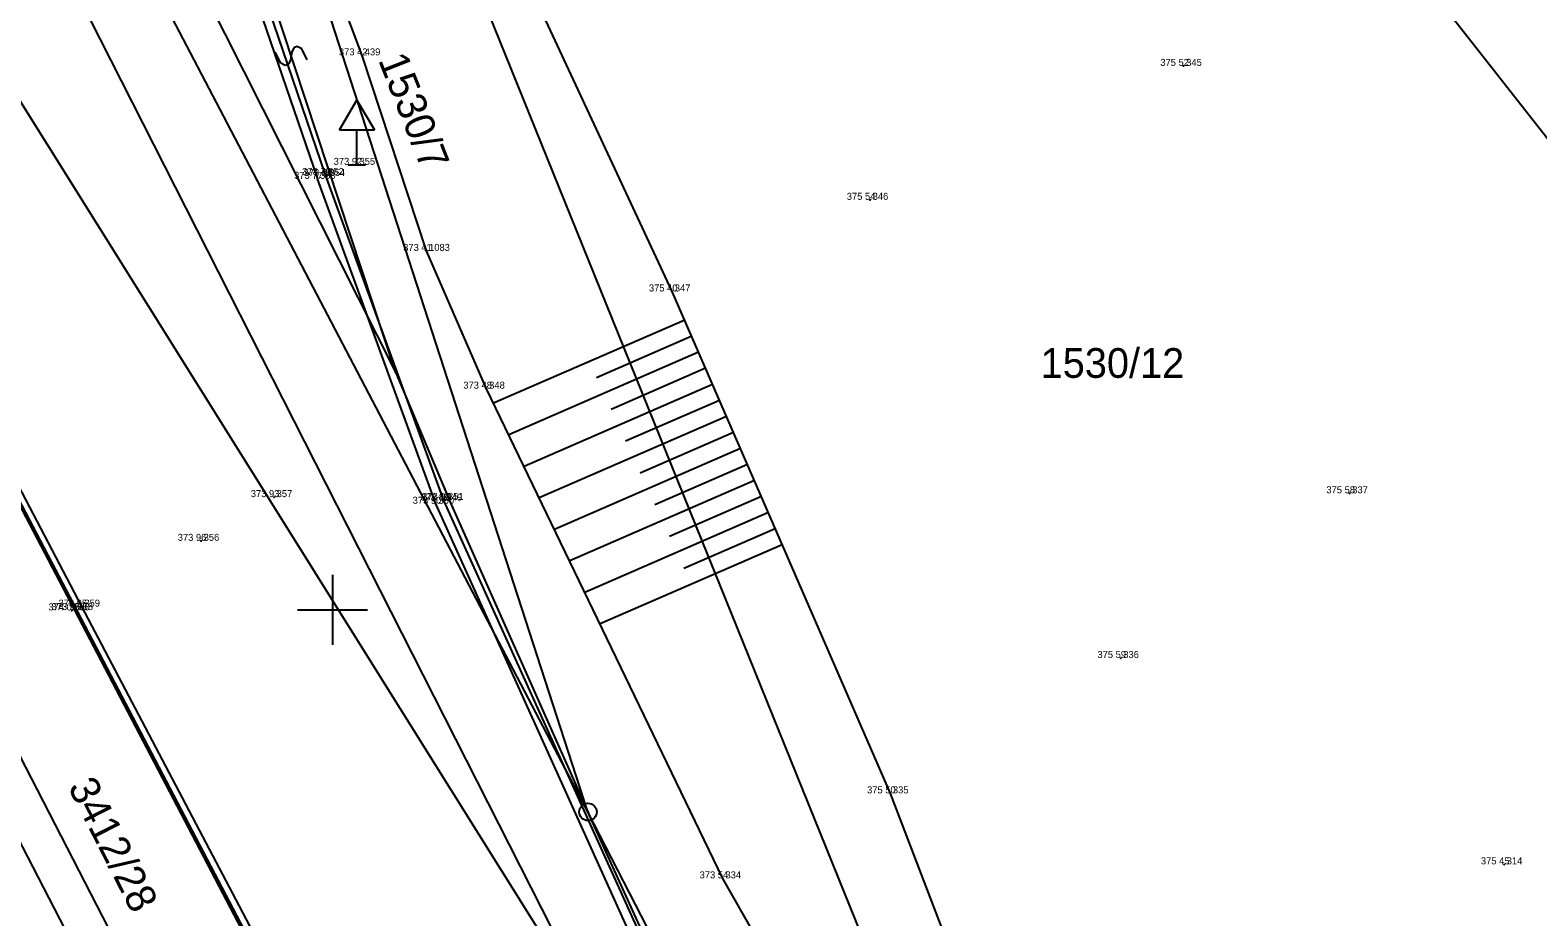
# Model space of a CAD drawing. Extents: x -601196 to -600262, y -1082523 to -1081922.
# Drawn here: x -600508.65 to -600465.52, y -1082258.78 to -1082233.43 of the extents above; entities that cross this region are included whole.
import ezdxf

# ---------------------------------------------------------------- set-up
doc = ezdxf.new("R2010")
doc.units = 0
for name, color, linetype in [('Vrstva 1', 7, 'Continuous'), ('Vrstva 10', 7, 'Continuous'), ('Vrstva 11', 7, 'Continuous'), ('Vrstva 14', 7, 'Continuous'), ('Vrstva 2', 7, 'Continuous'), ('Vrstva 20', 7, 'Continuous'), ('Vrstva 25', 7, 'Continuous'), ('Vrstva 3', 7, 'Continuous'), ('Vrstva 34', 7, 'Continuous'), ('Vrstva 47', 7, 'Continuous'), ('Vrstva 61', 7, 'Continuous')]:
    doc.layers.add(name, color=color, linetype=linetype)

msp = doc.modelspace()

# ---------------------------------------------------------------- linework, layer by layer
at = {"layer": 'Vrstva 1'}
for p, q in [((-600499.15, -1082234.15), (-600499.15, -1082234.15)), ((-600475.65, -1082234.45), (-600475.65, -1082234.45)), ((-600499.3, -1082237.28), (-600499.3, -1082237.28)), ((-600500.43, -1082237.68), (-600500.43, -1082237.68)), ((-600500.2, -1082237.57), (-600500.2, -1082237.57)), ((-600500.16, -1082237.6), (-600500.16, -1082237.6)), ((-600484.62, -1082238.28), (-600484.62, -1082238.28)), ((-600497.31, -1082239.74), (-600497.31, -1082239.74)), ((-600490.28, -1082240.9), (-600490.28, -1082240.9)), ((-600495.59, -1082243.68), (-600495.59, -1082243.68)), ((-600501.67, -1082246.78), (-600501.67, -1082246.78)), ((-600496.81, -1082246.88), (-600496.81, -1082246.88)), ((-600496.77, -1082246.86), (-600496.77, -1082246.86)), ((-600470.9, -1082246.67), (-600470.9, -1082246.67)), ((-600497.04, -1082246.97), (-600497.04, -1082246.97)), ((-600503.76, -1082248.03), (-600503.76, -1082248.03)), ((-600507.17, -1082249.91), (-600507.17, -1082249.91)), ((-600507.46, -1082250.02), (-600507.46, -1082250.02)), ((-600507.37, -1082250.01), (-600507.37, -1082250.01)), ((-600477.45, -1082251.38), (-600477.45, -1082251.38)), ((-600484.04, -1082255.25), (-600484.04, -1082255.25)), ((-600466.48, -1082257.28), (-600466.48, -1082257.28)), ((-600488.83, -1082257.68), (-600488.83, -1082257.68))]:
    msp.add_line(p, q, dxfattribs=at)
at = {"layer": 'Vrstva 10'}
for p, q in [((-600507.37, -1082250.01), (-600522.24, -1082221.66)), ((-600500.2, -1082237.57), (-600505.08, -1082223.28)), ((-600496.81, -1082246.88), (-600500.2, -1082237.57)), ((-600489.75, -1082262.47), (-600496.81, -1082246.88)), ((-600498.3, -1082267.34), (-600507.37, -1082250.01))]:
    msp.add_line(p, q, dxfattribs=at)
at = {"layer": 'Vrstva 11'}
for p, q in [((-600507.17, -1082249.91), (-600522.03, -1082221.55)), ((-600505.32, -1082223.38), (-600500.43, -1082237.68)), ((-600497.04, -1082246.97), (-600500.43, -1082237.68)), ((-600489.97, -1082262.62), (-600497.04, -1082246.97)), ((-600498.04, -1082267.25), (-600507.17, -1082249.91))]:
    msp.add_line(p, q, dxfattribs=at)
at = {"layer": 'Vrstva 14'}
for p, q in [((-600499.15, -1082234.15), (-600503.12, -1082223.58)), ((-600490.28, -1082240.9), (-600494.69, -1082231.44)), ((-600497.31, -1082239.74), (-600499.15, -1082234.15)), ((-600495.59, -1082243.68), (-600497.31, -1082239.74)), ((-600484.04, -1082255.25), (-600490.28, -1082240.9)), ((-600488.83, -1082257.68), (-600495.59, -1082243.68)), ((-600480.39, -1082264.78), (-600484.04, -1082255.25)), ((-600483.98, -1082266.22), (-600488.83, -1082257.68))]:
    msp.add_line(p, q, dxfattribs=at)
at = {"layer": 'Vrstva 20'}
for p, q in [((-600475.66, -1082234.45), (-600475.64, -1082234.45)), ((-600475.65, -1082234.435), (-600475.65, -1082234.45)), ((-600475.65, -1082234.465), (-600475.65, -1082234.45)), ((-600500.17, -1082237.6), (-600500.15, -1082237.6)), ((-600500.16, -1082237.585), (-600500.16, -1082237.6)), ((-600500.16, -1082237.615), (-600500.16, -1082237.6)), ((-600484.63, -1082238.28), (-600484.61, -1082238.28)), ((-600484.62, -1082238.265), (-600484.62, -1082238.28)), ((-600484.62, -1082238.295), (-600484.62, -1082238.28)), ((-600501.68, -1082246.78), (-600501.66, -1082246.78)), ((-600501.67, -1082246.765), (-600501.67, -1082246.78)), ((-600501.67, -1082246.795), (-600501.67, -1082246.78)), ((-600496.78, -1082246.86), (-600496.76, -1082246.86)), ((-600496.77, -1082246.845), (-600496.77, -1082246.86)), ((-600496.77, -1082246.875), (-600496.77, -1082246.86)), ((-600470.91, -1082246.67), (-600470.89, -1082246.67)), ((-600470.9, -1082246.655), (-600470.9, -1082246.67)), ((-600470.9, -1082246.685), (-600470.9, -1082246.67)), ((-600503.77, -1082248.03), (-600503.75, -1082248.03)), ((-600503.76, -1082248.015), (-600503.76, -1082248.03)), ((-600503.76, -1082248.045), (-600503.76, -1082248.03)), ((-600507.47, -1082250.02), (-600507.45, -1082250.02)), ((-600507.46, -1082250.005), (-600507.46, -1082250.02)), ((-600507.46, -1082250.035), (-600507.46, -1082250.02)), ((-600477.46, -1082251.38), (-600477.44, -1082251.38)), ((-600477.45, -1082251.365), (-600477.45, -1082251.38)), ((-600477.45, -1082251.395), (-600477.45, -1082251.38)), ((-600466.49, -1082257.28), (-600466.47, -1082257.28)), ((-600466.48, -1082257.265), (-600466.48, -1082257.28)), ((-600466.48, -1082257.295), (-600466.48, -1082257.28))]:
    msp.add_line(p, q, dxfattribs=at)
at = {"layer": 'Vrstva 25'}
for p, q in [((-600489.923, -1082241.722), (-600495.388, -1082244.098)), ((-600489.723, -1082242.18), (-600492.447, -1082243.365)), ((-600489.524, -1082242.639), (-600494.953, -1082245)), ((-600489.324, -1082243.097), (-600492.03, -1082244.274)), ((-600489.125, -1082243.556), (-600494.518, -1082245.901)), ((-600488.926, -1082244.014), (-600491.613, -1082245.183)), ((-600488.726, -1082244.473), (-600494.082, -1082246.802)), ((-600488.527, -1082244.931), (-600491.196, -1082246.092)), ((-600488.328, -1082245.39), (-600493.647, -1082247.703)), ((-600488.128, -1082245.849), (-600490.779, -1082247.001)), ((-600487.929, -1082246.307), (-600493.212, -1082248.604)), ((-600487.729, -1082246.766), (-600490.362, -1082247.91)), ((-600487.53, -1082247.224), (-600492.777, -1082249.506)), ((-600487.331, -1082247.683), (-600489.945, -1082248.819)), ((-600487.131, -1082248.141), (-600492.342, -1082250.407))]:
    msp.add_line(p, q, dxfattribs=at)
at = {"layer": 'Vrstva 34'}
for p, q in [((-600499.8, -1082236.28), (-600499.3, -1082235.43)), ((-600499.3, -1082235.43), (-600498.8, -1082236.28)), ((-600499.8, -1082236.28), (-600498.8, -1082236.28)), ((-600499.3, -1082237.28), (-600499.3, -1082236.28)), ((-600499.55, -1082237.28), (-600499.05, -1082237.28))]:
    msp.add_line(p, q, dxfattribs=at)
at = {"layer": 'Vrstva 47'}
for p, q in [((-600531.21, -1082199.91), (-600493.08, -1082260.78)), ((-600453.37, -1082251.69), (-600493.6, -1082200.35)), ((-600518.58, -1082202.79), (-600498.19, -1082243.23)), ((-600492.69, -1082255.78), (-600520.31, -1082203.04)), ((-600475.82, -1082281.64), (-600500.86, -1082219.77)), ((-600498.19, -1082243.23), (-600504.17, -1082225.11)), ((-600509.18, -1082228.7), (-600470.62, -1082304.61)), ((-600492.69, -1082255.78), (-600501.17, -1082229.64)), ((-600501.1, -1082233.933), (-600501.163, -1082234.059)), ((-600501.005, -1082233.901), (-600501.1, -1082233.933)), ((-600500.878, -1082233.965), (-600501.005, -1082233.901)), ((-600500.721, -1082234.282), (-600500.878, -1082233.965)), ((-600501.481, -1082234.374), (-600501.638, -1082234.057)), ((-600501.354, -1082234.438), (-600501.481, -1082234.374)), ((-600501.259, -1082234.406), (-600501.354, -1082234.438)), ((-600501.196, -1082234.28), (-600501.259, -1082234.406)), ((-600501.163, -1082234.059), (-600501.196, -1082234.28)), ((-600508.1, -1082258.25), (-600516.06, -1082242.9)), ((-600498.19, -1082243.23), (-600496.63, -1082246.92)), ((-600498.54, -1082266.73), (-600510.4, -1082244.12)), ((-600496.63, -1082246.92), (-600492.69, -1082255.78)), ((-600499.19, -1082273.1), (-600510.32, -1082251.5)), ((-600484.21, -1082274.45), (-600492.69, -1082255.78)), ((-600477.94, -1082284.47), (-600492.69, -1082255.78)), ((-600499.32, -1082275.25), (-600508.1, -1082258.25))]:
    msp.add_line(p, q, dxfattribs=at)
for radius in [0.25, 0.005]:
    msp.add_circle((-600492.69, -1082255.78), radius, dxfattribs=at)
at = {"layer": 'Vrstva 61'}
for p, q in [((-600500, -1082249), (-600500, -1082251)), ((-600500, -1082249), (-600500, -1082251)), ((-600501, -1082250), (-600499, -1082250)), ((-600501, -1082250), (-600499, -1082250))]:
    msp.add_line(p, q, dxfattribs=at)

# ---------------------------------------------------------------- texts
at = {"layer": 'Vrstva 2'}
for s, p in [(' 439', (-600499.15, -1082234.15)), (' 345', (-600475.65, -1082234.45)), (' 352', (-600500.2, -1082237.57)), (' 354', (-600500.16, -1082237.6)), (' 355', (-600499.3, -1082237.28)), (' 353', (-600500.43, -1082237.68)), (' 346', (-600484.62, -1082238.28)), (' 1083', (-600497.31, -1082239.74)), (' 347', (-600490.28, -1082240.9)), (' 348', (-600495.59, -1082243.68)), (' 337', (-600470.9, -1082246.67)), (' 357', (-600501.67, -1082246.78)), (' 350', (-600497.04, -1082246.97)), (' 349', (-600496.81, -1082246.88)), (' 351', (-600496.77, -1082246.86)), (' 356', (-600503.76, -1082248.03)), (' 360', (-600507.46, -1082250.02)), (' 358', (-600507.37, -1082250.01)), (' 359', (-600507.17, -1082249.91)), (' 336', (-600477.45, -1082251.38)), (' 335', (-600484.04, -1082255.25)), (' 314', (-600466.48, -1082257.28)), (' 334', (-600488.83, -1082257.68))]:
    msp.add_text(s, height=0.2, dxfattribs=at).set_placement(p)
at = {"layer": 'Vrstva 3'}
for s, p in [('373 42 ', (-600499.816, -1082234.15)), ('375 52 ', (-600476.316, -1082234.45)), ('373 79 ', (-600500.866, -1082237.57)), ('373 88 ', (-600500.826, -1082237.6)), ('373 92 ', (-600499.966, -1082237.28)), ('373 77 ', (-600501.096, -1082237.68)), ('375 54 ', (-600485.286, -1082238.28)), ('373 41 ', (-600497.976, -1082239.74)), ('375 40 ', (-600490.946, -1082240.9)), ('373 48 ', (-600496.256, -1082243.68)), ('375 58 ', (-600471.566, -1082246.67)), ('373 93 ', (-600502.336, -1082246.78)), ('373 90 ', (-600497.706, -1082246.97)), ('373 88 ', (-600497.476, -1082246.88)), ('373 98 ', (-600497.436, -1082246.86)), ('373 96 ', (-600504.426, -1082248.03)), ('374 05 ', (-600508.126, -1082250.02)), ('373 95 ', (-600508.036, -1082250.01)), ('373 95 ', (-600507.836, -1082249.91)), ('375 59 ', (-600478.116, -1082251.38)), ('375 50 ', (-600484.706, -1082255.25)), ('375 45 ', (-600467.146, -1082257.28)), ('373 54 ', (-600489.496, -1082257.68))]:
    msp.add_text(s, height=0.2, dxfattribs=at).set_placement(p)
at = {"layer": 'Vrstva 47'}
for s, rotation, p in [('1530/7', 291.6, (-600498.7, -1082234.28)), ('3412/28', 297, (-600507.581, -1082255.067))]:
    msp.add_text(s, height=0.85, rotation=rotation, dxfattribs=at).set_placement(p)
msp.add_text('1530/12', height=0.85, dxfattribs=at).set_placement((-600479.741, -1082243.37))

doc.saveas('drawing.dxf')
